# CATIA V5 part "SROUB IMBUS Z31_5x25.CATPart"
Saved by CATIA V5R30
Part number: SROUB IMBUS Z31/5x25
Bounding box of the stored display mesh (mm): x -5 to 25, y -4.24 to 4.24, z -4.25 to 4.25
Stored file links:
  C:\Users\ondra\Desktop\PŘÍLOHA P III\CATIA\SROUB IMBUS Z31_5x25.CATPart
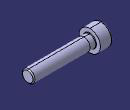
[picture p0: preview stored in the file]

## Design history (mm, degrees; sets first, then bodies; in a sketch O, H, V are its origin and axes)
Set1
  DatumSurface1 to DatumSurface29 "Z31/5x25"
  Join1: Elements (DatumSurface1; DatumSurface2; DatumSurface3; DatumSurface4; DatumSurface5; DatumSurface6; DatumSurface7; DatumSurface8; DatumSurface9; DatumSurface10; DatumSurface11; DatumSurface12; DatumSurface13; DatumSurface14; DatumSurface15; DatumSurface16; DatumSurface17; DatumSurface18; DatumSurface19; DatumSurface20; DatumSurface21; DatumSurface22; DatumSurface23; DatumSurface24; DatumSurface25; DatumSurface26; DatumSurface27; DatumSurface28; DatumSurface29)
Set2 "Geometry Failure"
  Set3 "FaceKO#Z31/5x25#409"
    DatumSurface30 "Sur409_1"
    Circle1 "Crv409_1": stored without definition
    DatumCurve1 "PCrv409_1"
    Circle2 "Crv409_2": stored without definition
    DatumCurve2 "PCrv409_2"
    Circle3 "Crv409_3": stored without definition
    DatumCurve3 "PCrv409_3"
    Circle4 "Crv409_4": stored without definition
    DatumCurve4 "PCrv409_4"
Body1 (main body)
  CloseSurface1: CloseElement Join1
